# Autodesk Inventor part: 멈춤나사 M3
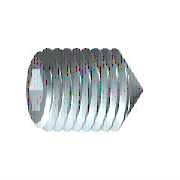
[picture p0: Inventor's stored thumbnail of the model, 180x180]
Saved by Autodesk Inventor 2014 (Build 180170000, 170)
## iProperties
IsCustomPart: 1
Created: 2012-02
Part Number: 멈춤나사 M3
Material: 강철, 연강
Description: 6각 소켓 머리 없는 멈춤 나사
Document SubType Name: Modeling
Standard: KS B 1028
Designer: test
Standards Organization: KS
Language: ko-KR
Size Designation: 원추점 M3x8
Categories: <MemberInstance><Categories><Category DisplayName="조임쇠" InternalName="e4da775c-781d-43d5-af7c-5136215cf5a6" Mnemonic="FSTN"><Category DisplayName="볼트" InternalN
Density: 1 g/cm^3
Appearance: 강철
Author: test
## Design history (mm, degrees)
sketch "스케치1"
  geometry: L1 (0, 0)-(5.5, 0); L2 (8, 0.866)-(8, 1.5); L3 (8, 1.5)-(0, 1.5); L4 (8, 0.866)-(6, 0.866); L5 (6, 0.866)-(5.5, 0); L6 (0, -0.3)-(0, 1.8) reference; L7 (0, 1.5)-(0, 0)
  constraints: 13 end point, 3 parallel, 1 collinear, 1 perpendicular, 1 point on line
  dimensions: "d0" = 2 distance of L2.start L4.end (= INTI); "d1" = 60 deg angle of L5 L1; "d2" = 3 diameter of L3 L1 (= NND); "d3" = 1.73205 diameter of L4 L1 (= 1.1547 x SW); "d5" = 8 distance from line of L2 L3.end (= NLG)
revolve "본체" sketch "스케치1" stored, may be unused: angle "d6" = 90 deg
sketch "스케치2"
  geometry: L1 (-0.433, 0.75)-(0.433, 0.75); L2 (0.433, 0.75)-(0.866, 0); L3 (0.866, 0)-(0.433, -0.75); L4 (0.433, -0.75)-(-0.433, -0.75); L5 (-0.433, -0.75)-(-0.866, 0); L6 (-0.866, 0)-(-0.433, 0.75); 3 further points
  constraints: 12 end point, 1 coincident, 1 horizontal, 13 other
extrude "슬롯" join sketch "스케치2" taper "d7" = 0 deg; stored distance "d21" = 10
workaxis "Work Axis1"
workplane "Work Plane1"
sketch "스케치4"
  geometry: L1 (0, 0.15)-(-1.35, 1.5) reference; L2 (0, -0.15)-(-1.35, -1.5) reference; L3 (-1.35, -1.5)-(0.15, 0); L4 (-1.35, 1.5)-(0.15, 0); 2 further points
  constraints: 4 end point, 1 coincident, 1 collinear, 1 horizontal alignment
body "Solid1"
feature "스레드" dims "d12" = 8 (= NLG), "d13" = 0
chamfer "모따기1" distance "d8" = 1.35 (computed from NND, SPD, FAWI); stored, may be unused: angle "d9" = 45 deg (= FAWI), second distance "d34" = 1.35 (computed from NND, SPD, FAWI)
chamfer "모따기2" distance "d10" = 0.30673 (= -0.5 x GD1 + 0.5 x NND); stored, may be unused: angle "d11" = 45 deg (= FAWI), second distance "d35" = 0.30673 (= -0.5 x GD1 + 0.5 x NND)
other parameters: "NND" = 3 [user parameter; used in 5 equation terms], "NLG" = 8 [user parameter; used in 2 equation terms], "INTI" = 2 [user parameter; used in 1 equation term], "FAWI" = 45 deg [user parameter; used in 4 equation terms], "SW" = 1.5 [user parameter; used in 2 equation terms], "GD1" = 2.38655 (= THREADDIA - 1.2269 x PTC) [user parameter; used in 2 equation terms], "d4" = 0, "FAWI1" = 45 deg [user parameter], "SPD" = 0.3 [user parameter; used in 2 equation terms], "d36" = 0, "d37" = 0, "GUL" = 0.30673 (= 0.61345 x PTC) [user parameter], "TOA" = 30 deg [user parameter], "THREADDIA" = 3 [user parameter; used in 1 equation term], "PTC" = 0.5 [user parameter; used in 4 equation terms], "GAL" = 0.30673 (= 0.61345 x PTC) [user parameter], "E0" = 1.7325 (= 1.155 x SW) [user parameter]
